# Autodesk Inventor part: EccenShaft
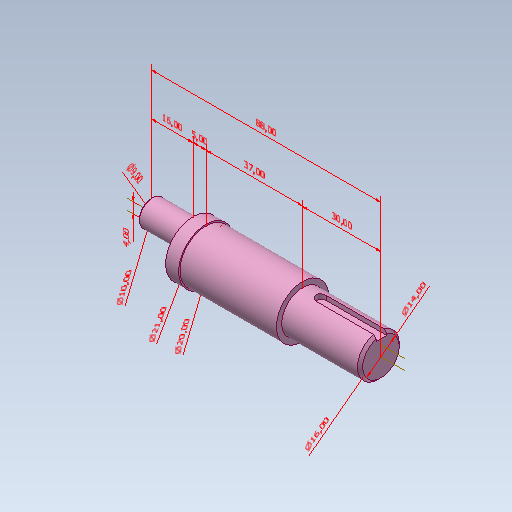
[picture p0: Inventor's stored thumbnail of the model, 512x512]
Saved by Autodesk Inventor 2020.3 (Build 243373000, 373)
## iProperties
Created: 2010-08
Part Number: EccenShaft
Document SubType Name: Modeling
Designer: nguyenducthang
Density: 1 g/cm^3
Mass: 20.4302 g
Surface Area: 54.0226 cm^2
Volume: 20.4302 cm^3
Material: Generico
Appearance: Bubblegum
Author: nguyenducthang
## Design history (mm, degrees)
node "Annotazioni"
  node "Quota lineare 1" dims "d454" = 10.5, "d456" = 10, "d457" = 8, "d458" = 5, "d461" = 30, "d564" = 4 (derived)
  node "Quota lineare 2" dims "d454" = 10.5, "d456" = 10, "d457" = 8, "d458" = 5, "d461" = 30, "d565" = 88 (derived)
  node "Quota lineare 3" dims "d454" = 10.5, "d456" = 10, "d457" = 8, "d458" = 5, "d461" = 30, "d566" = 30 (derived)
  node "Quota lineare 4" dims "d454" = 10.5, "d456" = 10, "d457" = 8, "d458" = 5, "d461" = 30, "d567" = 37 (derived)
  node "Quota lineare 5" dims "d454" = 10.5, "d456" = 10, "d457" = 8, "d458" = 5, "d461" = 30, "d568" = 5 (derived)
  node "Quota lineare 6" dims "d454" = 10.5, "d456" = 10, "d457" = 8, "d458" = 5, "d461" = 30, "d569" = 16 (derived)
  node "Quota diametro 1" dims "d454" = 10.5, "d456" = 10, "d457" = 8, "d458" = 5, "d461" = 30, "d571" = 10 (derived)
  node "Quota diametro 2" dims "d454" = 10.5, "d456" = 10, "d457" = 8, "d458" = 5, "d461" = 30, "d573" = 21 (derived)
  node "Quota diametro 3" dims "d454" = 10.5, "d456" = 10, "d457" = 8, "d458" = 5, "d461" = 30, "d577" = 20 (derived)
  node "Quota diametro 4" dims "d454" = 10.5, "d456" = 10, "d457" = 8, "d458" = 5, "d461" = 30, "d579" = 16 (derived)
  node "Quota diametro 5" dims "d454" = 10.5, "d456" = 10, "d457" = 8, "d458" = 5, "d461" = 30, "d581" = 9 (derived)
  node "Quota diametro 6" dims "d454" = 10.5, "d456" = 10, "d457" = 8, "d458" = 5, "d461" = 30, "d583" = 14 (derived)
revolve "Revolution7" stored, may be unused: angle "d462" = 90 deg
chamfer "Chamfer23" distance "d540" = 1; stored, may be unused: second distance "d541" = 2, angle "d542" = 45 deg
sketch "Sketch78"
  geometry: L1 (-1.8, 6)-(2.2, 6); L2 (2.2, 6)-(2.2, 8.694); L3 (2.2, 8.694)-(-1.8, 8.694); L4 (-1.8, 8.694)-(-1.8, 6); C1 r 7 at (0.2, 0)
  constraints: 8 end point, 2 parallel, 1 centre point, 1 horizontal, 1 perpendicular
  dimensions: "d543" = 6 distance from line of L1 C1.centre; "d544" = 4 distance of L2.end L3.end; "d545" = 2 distance from line of L2 C1.centre
extrude "Extrusion63" cut sketch "Sketch78" distance "d546" = 25; taper "d547" = 0 deg
fillet "Fillet19" dims "d548" = 2
sketch "Sketch79"
  geometry: C1 r 10.5 at (0, 0) reference; C2 r 5 at (0, 4)
  constraints: 1 centre point
  dimensions: "d552" = 4 distance of C2.centre C1.centre; "d553" = 10 diameter of C2
extrude "Extrusion64" join sketch "Sketch79" distance "d554" = 16; taper "d555" = 0 deg
chamfer "Chamfer25" distance "d559" = 0.5; stored, may be unused: second distance "d560" = 2, angle "d561" = 45 deg
node "Asse di lavoro2"
node "Asse di lavoro3"
node "Solido1"
node "Corpi solidi"
node "Corpi di superficie"
sketch "Sketch69"
  geometry: L1 (0, 0)-(0, 10.5); L2 (0, 10.5)-(5, 10.5); L3 (5, 10.5)-(5, 10); L4 (5, 10)-(42, 10); L5 (42, 10)-(42, 8); L6 (42, 8)-(72, 8); L7 (72, 8)-(72, 0); L8 (72, 0)-(0, 0); 1 further point
  constraints: 16 end point, 6 parallel, 1 perpendicular, 1 point on line, 1 vertical, 1 other
  dimensions: "d454" = 10.5 distance of L1.start L1.end; "d456" = 10 distance between parallel lines of L4 L8; "d457" = 8 distance between parallel lines of L6 L8; "d458" = 5 distance of L1.end L2.end; "d461" = 30 distance of L5.end L6.end
other parameters: "d489" = 5.6, "d562" = -81.10459 (derived), "d563" = -8.02499 (derived), "d570" = 19.61435 (derived), "d572" = 4.19242 (derived), "d574" = 24.88761 (derived), "d575" = 0.54102 (derived), "d576" = 4.98743 (derived), "d578" = 53.59174 (derived), "d580" = 26.11183 (derived), "d582" = 51.56356 (derived)
